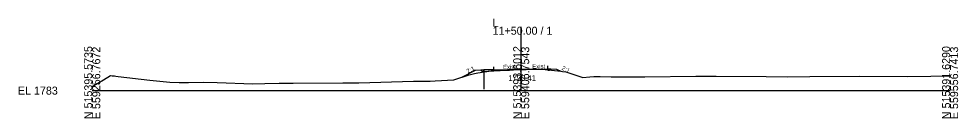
# Model space of a CAD drawing. Extents: x -26 to 1303, y -10 to 9545.
# Drawn here: x -25.7 to 302.8, y 3490.3 to 3525.2 of the extents above; entities that cross this region are included whole.
import ezdxf

# ---------------------------------------------------------------- set-up
doc = ezdxf.new("R2010")
doc.units = 0
for name, color, linetype in [('Exist Cross Section Cell', 7, 'Continuous'), ('Exist XS Center Line Elevation Label', 7, 'Continuous'), ('Exist XS Ground Line', 7, 'Continuous'), ('Prop XS Ditch Slope Text', 7, 'Continuous'), ('Prop XS EOT Tick Mark', 7, 'Continuous'), ('Prop XS Finish Grade', 7, 'Continuous'), ('Prop XS Finish Grade Earthwork', 7, 'Continuous'), ('Prop XS Finish Grade Paved Shoulder', 7, 'Continuous'), ('Prop XS Finish Grade Pavement', 7, 'Continuous'), ('Prop XS Pvmt Edge Slope', 7, 'Continuous'), ('Prop XS SE Text', 7, 'Continuous'), ('Prop XS Subgrade Earthwork', 7, 'Continuous'), ('Scratch_Level_3', 7, 'Continuous')]:
    doc.layers.add(name, color=color, linetype=linetype)

msp = doc.modelspace()

# ---------------------------------------------------------------- linework, layer by layer
at = {"layer": 'Exist Cross Section Cell'}
for p, q in [((150, 3500), (150, 3522.39)), ((0, 3500), (150, 3500)), ((150, 3500), (300, 3500))]:
    msp.add_line(p, q, dxfattribs=at)
at = {"layer": 'Exist XS Ground Line'}
for p, q in [((126.5, 3503.73), (131.85, 3505.49)), ((131.85, 3505.49), (133.63, 3506.04)), ((133.63, 3506.04), (134.87, 3506.25)), ((134.87, 3506.25), (139.49, 3506.94)), ((139.49, 3506.94), (145.87, 3507.22)), ((145.87, 3507.22), (148.84, 3507.4)), ((148.84, 3507.4), (150, 3507.41)), ((150, 3507.41), (151.76, 3507.42)), ((151.76, 3507.42), (157.33, 3507.46)), ((157.33, 3507.46), (163.87, 3506.77)), ((163.87, 3506.77), (164.49, 3506.75)), ((164.49, 3506.75), (165.67, 3506.54)), ((165.67, 3506.54), (169.48, 3505.27)), ((0, 3501.43), (3.94, 3503.83)), ((3.94, 3503.83), (6.41, 3505.27)), ((6.41, 3505.27), (6.96, 3505.21)), ((6.96, 3505.21), (7.76, 3505.12)), ((7.76, 3505.12), (8.28, 3505.04)), ((8.28, 3505.04), (9.11, 3504.95)), ((9.11, 3504.95), (20.18, 3503.61)), ((20.18, 3503.61), (27.16, 3503.01)), ((27.16, 3503.01), (30.4, 3502.87)), ((30.4, 3502.87), (33.71, 3502.88)), ((33.71, 3502.88), (38.9, 3502.91)), ((38.9, 3502.91), (43.67, 3502.79)), ((43.67, 3502.79), (56.1, 3502.34)), ((56.1, 3502.34), (60.4, 3502.44)), ((60.4, 3502.44), (65.31, 3502.56)), ((65.31, 3502.56), (70.22, 3502.62)), ((70.22, 3502.62), (87.67, 3502.68)), ((87.67, 3502.68), (93.24, 3502.67)), ((93.24, 3502.67), (112.32, 3503.29)), ((112.32, 3503.29), (118.21, 3503.31)), ((118.21, 3503.31), (119.92, 3503.4)), ((119.92, 3503.4), (126.5, 3503.73)), ((169.48, 3505.27), (171.52, 3504.56)), ((171.52, 3504.56), (173.96, 3504.81)), ((173.96, 3504.81), (175.45, 3504.96)), ((175.45, 3504.96), (177.58, 3504.91)), ((177.58, 3504.91), (181.46, 3504.84)), ((181.46, 3504.84), (185.4, 3504.85)), ((185.4, 3504.85), (193.28, 3504.85)), ((193.28, 3504.85), (211.05, 3505.01)), ((211.05, 3505.01), (218.25, 3505.01)), ((218.25, 3505.01), (235.73, 3504.92)), ((235.73, 3504.92), (243.24, 3504.87)), ((243.24, 3504.87), (250.99, 3504.91)), ((250.99, 3504.91), (268.26, 3505.01)), ((268.26, 3505.01), (285.09, 3504.98)), ((285.09, 3504.98), (293.25, 3505.02)), ((293.25, 3505.02), (300, 3505.14))]:
    msp.add_line(p, q, dxfattribs=at)
at = {"layer": 'Prop XS EOT Tick Mark'}
for p, q in [((140.44, 3507.31), (140.44, 3508.31)), ((159.31, 3507.69), (159.31, 3508.69))]:
    msp.add_line(p, q, dxfattribs=at)
at = {"layer": 'Prop XS Finish Grade'}
for p, q in [((136.92, 3507.23), (135.89, 3507.15)), ((159.31, 3507.69), (160.33, 3507.65))]:
    msp.add_line(p, q, dxfattribs=at)
at = {"layer": 'Prop XS Finish Grade Earthwork'}
for p, q in [((133.92, 3506.99), (129.1, 3504.58)), ((135.89, 3507.15), (133.92, 3506.99)), ((135.89, 3507.15), (135.89, 3507.15)), ((160.33, 3507.65), (162.31, 3507.53)), ((162.31, 3507.53), (163.82, 3506.77))]:
    msp.add_line(p, q, dxfattribs=at)
at = {"layer": 'Prop XS Finish Grade Paved Shoulder'}
msp.add_line((140.44, 3507.31), (136.92, 3507.23), dxfattribs=at)
at = {"layer": 'Prop XS Finish Grade Pavement'}
for p, q in [((140.44, 3507.31), (150, 3507.53)), ((150, 3507.53), (159.31, 3507.69))]:
    msp.add_line(p, q, dxfattribs=at)
at = {"layer": 'Prop XS Pvmt Edge Slope'}
for p, q in [((136.92, 3507.23), (136.47, 3506.57)), ((159.31, 3507.69), (159.84, 3507.16))]:
    msp.add_line(p, q, dxfattribs=at)
at = {"layer": 'Prop XS Subgrade Earthwork'}
for p, q in [((136.47, 3506.57), (135.89, 3507.15)), ((140.44, 3506.76), (136.47, 3506.57)), ((140.44, 3506.76), (140.44, 3506.98)), ((159.31, 3507.15), (159.31, 3507.31)), ((159.31, 3507.15), (159.84, 3507.16)), ((159.84, 3507.16), (160.33, 3507.65))]:
    msp.add_line(p, q, dxfattribs=at)
at = {"layer": 'Scratch_Level_3'}
msp.add_line((136.92, 3507.31), (136.92, 3500.52), dxfattribs=at)

# ---------------------------------------------------------------- texts
at = {"layer": 'Exist Cross Section Cell'}
for s, p in [('L', (140, 3522.39)), ('11+50.00 / 1', (140, 3519.59)), ('EL 1783', (-26, 3498.6))]:
    msp.add_text(s, height=2.8, dxfattribs=at).set_placement(p)
for s, p in [('N 515395.5735', (0, 3490)), ('N 515393.6012', (150, 3490)), ('N 515391.6290', (300, 3490)), ('E 559256.7672', (2.8, 3490)), ('E 559406.7543', (152.8, 3490)), ('E 559556.7413', (302.8, 3490))]:
    msp.add_text(s, height=2.8, rotation=90, dxfattribs=at).set_placement(p)
at = {"layer": 'Exist XS Center Line Elevation Label'}
msp.add_text('1790.41', height=2, dxfattribs=at).set_placement((145.51, 3503.41))
at = {"layer": 'Prop XS Ditch Slope Text'}
for rotation, p in [(26.5651, (131.32, 3506.02)), (333.4349, (164.01, 3507.41))]:
    msp.add_text('2:1', height=1.5, rotation=rotation, dxfattribs=at).set_placement(p)
at = {"layer": 'Prop XS SE Text'}
for p in [(143.68, 3507.52), (153.9, 3507.71)]:
    msp.add_text('Exist', height=1.5, rotation=1.3214, dxfattribs=at).set_placement(p)

doc.saveas('drawing.dxf')
